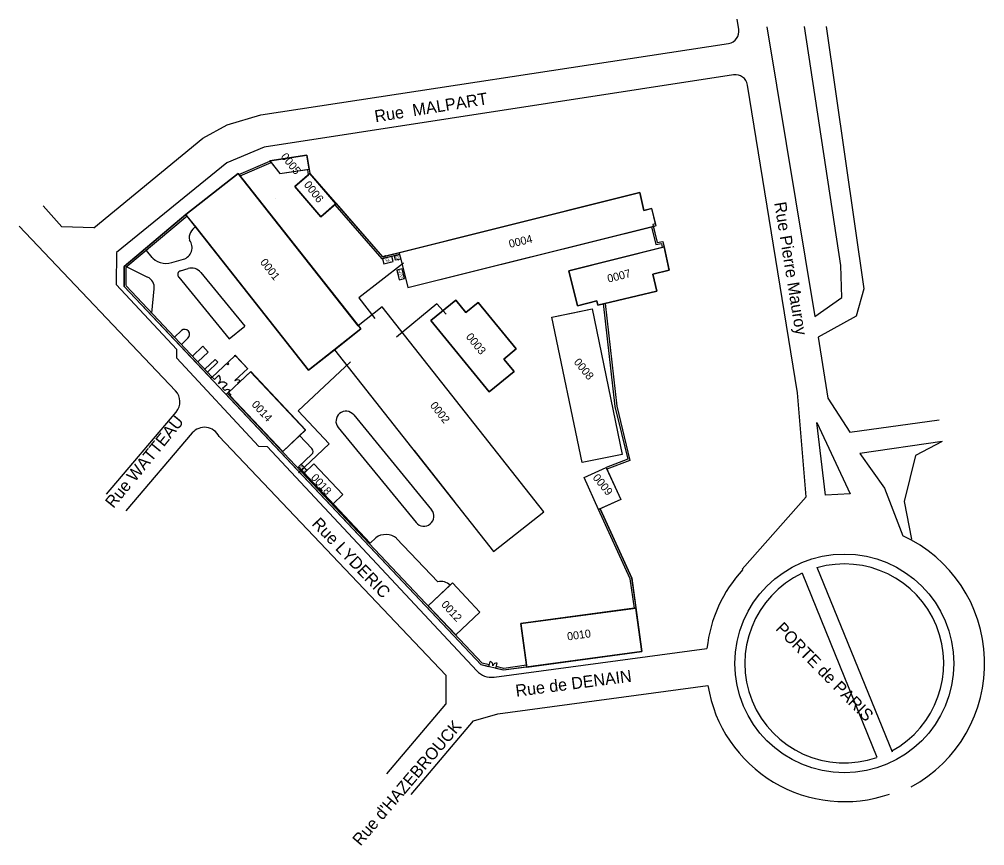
# Model space of a CAD drawing. Extents: x 703432 to 707394, y 7057985 to 7059523.
# Drawn here: x 703431.9 to 703673.1, y 7057985.3 to 7058191.7 of the extents above; entities that cross this region are included whole.
import ezdxf

# ---------------------------------------------------------------- set-up
doc = ezdxf.new("R2010")
doc.units = 0
for name, color, linetype in [('DH_HACHURE-MOTIF', 7, 'Continuous'), ('DH_TEXTE', 7, 'Continuous'), ('GEOSID_AIRE_AMENAGEE_POLYGONE', 7, 'Continuous'), ('GO_DALLE', 7, 'Continuous'), ('GO_MUR_EXTERIEUR', 7, 'Continuous'), ('IMM_LIMITE PHYSIQUE', 7, 'Continuous'), ('R_CH_PRIM_CANALISATION_CL_A', 7, 'Continuous'), ('R_IND_GAZ_NAT_CANALISATION_CL_A', 7, 'Continuous'), ('R_PLU_CANALISATION_CL_A', 7, 'Continuous'), ('RES_INCENDIE - EQUIP - TEXTE', 7, 'Continuous'), ('SID_NUMERO_BATI', 7, 'Continuous'), ('SID_POLYLIGNES_BATI', 7, 'Continuous'), ('SID_POLYLIGNES_IMMEUBLE', 7, 'Continuous'), ('VOIRIE_BORDURE', 7, 'Continuous'), ('VOIRIE_ROUTE', 7, 'Continuous')]:
    doc.layers.add(name, color=color, linetype=linetype)

msp = doc.modelspace()

# ---------------------------------------------------------------- linework, layer by layer
at = {"layer": 'DH_HACHURE-MOTIF'}
for p, q in [((703500.68, 7058149.94), (703504.1, 7058152.86)), ((703504.1, 7058152.86), (703504.48, 7058153.19)), ((703504.48, 7058153.19), (703510.98, 7058145.59)), ((703507.18, 7058142.34), (703500.68, 7058149.94)), ((703564.97, 7058117.3), (703569.88, 7058118.25)), ((703572.51, 7058080.96), (703564.97, 7058117.3)), ((703582.53, 7058082.98), (703572.51, 7058080.96)), ((703573, 7058077.21), (703578.53, 7058079.71)), ((703576.61, 7058069.22), (703573, 7058077.21)), ((703582.14, 7058071.72), (703576.61, 7058069.22))]:
    msp.add_line(p, q, dxfattribs=at)
for points in [[(703503.86, 7058154.19), (703504.3, 7058154.27), (703503.72, 7058157.72), (703494.45, 7058156.29), (703494.78, 7058155.89), (703497, 7058153.17), (703503.86, 7058154.19)], [(703473.77, 7058142.54), (703475.97, 7058139.76), (703504.16, 7058104.03), (703510.63, 7058109.14), (703517.19, 7058114.32), (703516.57, 7058115.1), (703486.83, 7058152.79), (703486.53, 7058153.18), (703473.5, 7058142.9), (703473.77, 7058142.54)], [(703526.88, 7058132.93), (703527.17, 7058131.79), (703528.95, 7058124.64), (703590.61, 7058140.04), (703591.04, 7058140.15), (703589.89, 7058144.43), (703587.95, 7058143.95), (703586.92, 7058148.4), (703550.06, 7058139.19), (703526.77, 7058133.37), (703526.88, 7058132.93)], [(703510.98, 7058145.59), (703510.64, 7058145.3), (703507.18, 7058142.34)], [(703576.15, 7058121.35), (703576.39, 7058120.28), (703591.14, 7058123.77), (703590.14, 7058127.99), (703594.28, 7058129.02), (703592.96, 7058134.81), (703592.52, 7058134.7), (703569.18, 7058128.87), (703571.36, 7058120.14), (703576.15, 7058121.35)], [(703524.99, 7058132.46), (703522.61, 7058131.86), (703522.93, 7058130.57), (703525.31, 7058131.17), (703524.99, 7058132.46)], [(703526.82, 7058126.62), (703528.11, 7058126.94), (703527.52, 7058129.32), (703526.23, 7058129), (703526.82, 7058126.62)], [(703543.45, 7058118.42), (703540.91, 7058121.51), (703534.72, 7058116.44), (703549.3, 7058098.65), (703555.49, 7058103.72), (703552.95, 7058106.82), (703556.05, 7058109.35), (703546.54, 7058120.95), (703543.45, 7058118.42)], [(703562.95, 7058068.66), (703522.57, 7058119.84), (703516.57, 7058115.1), (703517.19, 7058114.32), (703510.63, 7058109.14), (703550.39, 7058058.75), (703562.95, 7058068.66)], [(703569.88, 7058118.25), (703574.99, 7058119.31), (703582.53, 7058082.98)], [(703502.39, 7058080.46), (703502.33, 7058080.54), (703501.6, 7058079.85), (703503.02, 7058078.34), (703503.75, 7058079.03), (703502.39, 7058080.46)], [(703578.53, 7058079.71), (703578.62, 7058079.51), (703582.14, 7058071.72)], [(703539.51, 7058050.32), (703534.05, 7058045.16), (703540.91, 7058037.89), (703546.96, 7058043.59), (703540.1, 7058050.87), (703539.51, 7058050.32)], [(703558.6, 7058030.31), (703558.66, 7058029.86), (703587.4, 7058033.72), (703585.94, 7058044.62), (703585.49, 7058044.56), (703557.2, 7058040.77), (703558.6, 7058030.31)]]:
    msp.add_lwpolyline(points, dxfattribs=at)
for points in [[(703499.64, 7058085.57), (703503.36, 7058089.08), (703489.64, 7058103.63), (703484.12, 7058098.42), (703484.71, 7058097.8), (703484.54, 7058097.64), (703497.68, 7058083.71)], [(703505.47, 7058080.66), (703503.02, 7058078.34), (703510.26, 7058070.67), (703512.71, 7058072.98)]]:
    msp.add_lwpolyline(points, close=True, dxfattribs=at)
at = {"layer": 'GEOSID_AIRE_AMENAGEE_POLYGONE'}
msp.add_lwpolyline([(703525.9, 7058131.48), (703525.62, 7058132.62), (703526.88, 7058132.93), (703527.16, 7058131.79)], close=True, dxfattribs=at)
at = {"layer": 'GO_DALLE'}
msp.add_lwpolyline([(703526.88, 7058132.93), (703527.17, 7058131.79), (703525.9, 7058131.48), (703525.62, 7058132.62)], close=True, dxfattribs=at)
at = {"layer": 'GO_MUR_EXTERIEUR'}
for p, q in [((703503.72, 7058157.72), (703494.45, 7058156.29)), ((703504.3, 7058154.27), (703503.72, 7058157.72)), ((703494.45, 7058156.29), (703497, 7058153.17)), ((703473.5, 7058142.9), (703486.53, 7058153.18)), ((703486.53, 7058153.18), (703517.19, 7058114.32)), ((703497, 7058153.17), (703504.3, 7058154.27)), ((703504.48, 7058153.19), (703500.68, 7058149.94)), ((703510.98, 7058145.59), (703504.48, 7058153.19)), ((703500.68, 7058149.94), (703507.18, 7058142.34)), ((703500.68, 7058149.94), (703500.68, 7058149.94)), ((703586.92, 7058148.4), (703526.77, 7058133.37)), ((703587.95, 7058143.95), (703586.92, 7058148.4)), ((703507.18, 7058142.34), (703510.98, 7058145.59)), ((703504.16, 7058104.03), (703473.5, 7058142.9)), ((703589.89, 7058144.43), (703587.95, 7058143.95)), ((703591.04, 7058140.15), (703589.89, 7058144.43)), ((703528.95, 7058124.64), (703591.04, 7058140.15)), ((703526.77, 7058133.37), (703528.95, 7058124.64)), ((703569.18, 7058128.87), (703592.96, 7058134.81)), ((703592.96, 7058134.81), (703594.28, 7058129.02)), ((703571.36, 7058120.14), (703569.18, 7058128.87)), ((703594.28, 7058129.02), (703590.14, 7058127.99)), ((703590.14, 7058127.99), (703591.14, 7058123.77)), ((703534.72, 7058116.44), (703540.91, 7058121.51)), ((703540.91, 7058121.51), (703543.45, 7058118.42)), ((703543.45, 7058118.42), (703546.54, 7058120.95)), ((703546.54, 7058120.95), (703556.05, 7058109.35)), ((703522.57, 7058119.84), (703516.57, 7058115.1)), ((703562.95, 7058068.66), (703522.57, 7058119.84)), ((703564.97, 7058117.3), (703574.99, 7058119.31)), ((703574.99, 7058119.31), (703582.53, 7058082.98)), ((703549.3, 7058098.65), (703534.72, 7058116.44)), ((703572.51, 7058080.96), (703564.97, 7058117.3)), ((703517.19, 7058114.32), (703504.16, 7058104.03)), ((703517.19, 7058114.32), (703510.63, 7058109.14)), ((703516.57, 7058115.1), (703517.19, 7058114.32)), ((703510.63, 7058109.14), (703550.39, 7058058.75)), ((703556.05, 7058109.35), (703552.95, 7058106.82)), ((703552.95, 7058106.82), (703555.49, 7058103.72)), ((703489.68, 7058103.66), (703484.12, 7058098.42)), ((703503.4, 7058089.11), (703489.68, 7058103.66)), ((703555.49, 7058103.72), (703549.3, 7058098.65)), ((703497.68, 7058083.71), (703503.4, 7058089.11)), ((703582.53, 7058082.98), (703572.51, 7058080.96)), ((703501.6, 7058079.85), (703502.33, 7058080.54)), ((703502.33, 7058080.54), (703503.75, 7058079.03)), ((703503.02, 7058078.34), (703501.6, 7058079.85)), ((703503.75, 7058079.03), (703503.02, 7058078.34)), ((703573, 7058077.21), (703578.53, 7058079.71)), ((703578.53, 7058079.71), (703582.14, 7058071.72)), ((703576.61, 7058069.22), (703573, 7058077.21)), ((703582.14, 7058071.72), (703576.61, 7058069.22)), ((703550.39, 7058058.75), (703562.95, 7058068.66)), ((703534.05, 7058045.16), (703540.1, 7058050.87)), ((703540.1, 7058050.87), (703546.96, 7058043.59)), ((703540.91, 7058037.89), (703534.05, 7058045.16)), ((703557.2, 7058040.77), (703585.94, 7058044.62)), ((703585.94, 7058044.62), (703587.4, 7058033.72)), ((703546.96, 7058043.59), (703540.91, 7058037.89)), ((703558.66, 7058029.86), (703557.2, 7058040.77)), ((703587.4, 7058033.72), (703558.66, 7058029.86))]:
    msp.add_line(p, q, dxfattribs=at)
for points in [[(703522.61, 7058131.86), (703522.93, 7058130.57), (703525.31, 7058131.17), (703524.99, 7058132.46)], [(703527.52, 7058129.32), (703526.23, 7058129), (703526.82, 7058126.62), (703528.11, 7058126.94)], [(703505.47, 7058080.66), (703512.71, 7058072.98), (703510.26, 7058070.67), (703503.02, 7058078.34)]]:
    msp.add_lwpolyline(points, close=True, dxfattribs=at)
for points in [[(703591.14, 7058123.77), (703576.39, 7058120.28), (703576.15, 7058121.35), (703571.36, 7058120.14)], [(703484.12, 7058098.42), (703484.71, 7058097.8), (703484.54, 7058097.64), (703497.68, 7058083.71)]]:
    msp.add_lwpolyline(points, dxfattribs=at)
at = {"layer": 'IMM_LIMITE PHYSIQUE'}
for p, q in [((703486.74, 7058152.92), (703494.47, 7058156.25)), ((703487.04, 7058152.56), (703494.78, 7058155.89)), ((703503.86, 7058154.19), (703504.08, 7058152.85)), ((703504.3, 7058154.27), (703504.48, 7058153.19)), ((703510.7, 7058145.35), (703522.43, 7058131.81)), ((703511.04, 7058145.64), (703522.58, 7058132.32)), ((703473.5, 7058142.89), (703458.07, 7058129.92)), ((703473.79, 7058142.54), (703458.52, 7058129.71)), ((703526.77, 7058133.37), (703522.58, 7058132.32)), ((703526.89, 7058132.93), (703522.43, 7058131.81)), ((703458.07, 7058129.92), (703458.07, 7058124.97)), ((703458.52, 7058129.71), (703458.52, 7058125.17)), ((703593.8, 7058129.52), (703593.8, 7058129.52)), ((703458.07, 7058124.97), (703479.74, 7058102)), ((703458.54, 7058125.13), (703480.07, 7058102.31)), ((703480.07, 7058102.31), (703485.63, 7058107.56)), ((703485.72, 7058101.42), (703488.93, 7058104.45)), ((703480.07, 7058102.31), (703479.74, 7058102)), ((703480.07, 7058102.3), (703480.62, 7058101.72)), ((703480.62, 7058101.72), (703481.71, 7058102.75)), ((703482.68, 7058099.54), (703483.77, 7058100.57)), ((703482.68, 7058099.54), (703483.23, 7058098.95)), ((703485.72, 7058101.42), (703485.78, 7058101.36)), ((703487.05, 7058101.32), (703486.4, 7058100.7)), ((703486.4, 7058100.7), (703486.45, 7058100.64)), ((703483.91, 7058098.24), (703483.58, 7058097.93)), ((703483.58, 7058097.93), (703547.28, 7058030.41)), ((703484.5, 7058098.92), (703483.85, 7058098.3)), ((703483.85, 7058098.3), (703483.91, 7058098.24)), ((703483.91, 7058098.24), (703547.51, 7058030.81)), ((703549.21, 7058029.95), (703547.28, 7058030.41)), ((703549.31, 7058030.39), (703547.51, 7058030.81)), ((703549.21, 7058029.95), (703549.51, 7058031.24)), ((703550.96, 7058029.54), (703551.26, 7058030.83)), ((703552.89, 7058029.09), (703550.96, 7058029.54)), ((703552.91, 7058029.55), (703551.06, 7058029.98)), ((703558.66, 7058029.86), (703552.89, 7058029.09)), ((703558.6, 7058030.31), (703552.91, 7058029.55))]:
    msp.add_line(p, q, dxfattribs=at)
for points in [[(703589.85, 7058139.86), (703590.9, 7058135.39), (703592.3, 7058135.66), (703592.52, 7058134.71)], [(703590.29, 7058139.97), (703591.24, 7058135.91), (703592.64, 7058136.18), (703592.96, 7058134.81)], [(703577.78, 7058120.66), (703580.7, 7058094.94), (703583.92, 7058081.77), (703578.54, 7058079.71)], [(703578.22, 7058120.72), (703581.14, 7058095.02), (703584.45, 7058081.49), (703578.7, 7058079.29)], [(703585.55, 7058044.57), (703584.53, 7058051.91), (703576.62, 7058069.19)], [(703586, 7058044.63), (703584.96, 7058052.04), (703577.03, 7058069.38)]]:
    msp.add_lwpolyline(points, dxfattribs=at)
for points in [[(703485.79, 7058107.7), (703485.55, 7058107.65), (703485.72, 7058107.46)], [(703485.79, 7058107.7), (703488.95, 7058104.35), (703488.99, 7058104.39), (703485.83, 7058107.74)], [(703483.76, 7058105.64), (703483.96, 7058105.42), (703484.2, 7058105.65), (703484, 7058105.87)]]:
    msp.add_lwpolyline(points, close=True, dxfattribs=at)
for centre, radius, start, end in [((703480.62, 7058101.72), 1.5, 313.3307, 43.3307), ((703482.68, 7058099.54), 1.5, 43.3307, 133.3307), ((703486.4, 7058100.7), 0.9, 43.3307, 133.3307), ((703483.85, 7058098.3), 0.9, 43.3307, 133.3307), ((703549.34, 7058030.39), 0.874, 346.7916, 78.7098), ((703551.04, 7058029.99), 0.874, 75.2683, 166.7916)]:
    msp.add_arc(centre, radius, start, end, dxfattribs=at)
at = {"layer": 'R_CH_PRIM_CANALISATION_CL_A'}
for points in [[(703527.83, 7058130.75), (703516.68, 7058122.14), (703520.71, 7058116.92)], [(703538.54, 7058118.06), (703536.19, 7058120.58), (703526.14, 7058112.25)]]:
    msp.add_lwpolyline(points, dxfattribs=at)
at = {"layer": 'R_IND_GAZ_NAT_CANALISATION_CL_A'}
msp.add_lwpolyline([(703501.61, 7058078.39), (703509.33, 7058085.59), (703501.56, 7058093.91), (703514.66, 7058106.14)], dxfattribs=at)
at = {"layer": 'R_PLU_CANALISATION_CL_A'}
msp.add_line((703530.51, 7058083.95), (703540.63, 7058071.12), dxfattribs=at)
at = {"layer": 'RES_INCENDIE - EQUIP - TEXTE'}
msp.add_line((703495.87, 7058146.98), (703495.87, 7058146.98), dxfattribs=at)
at = {"layer": 'SID_POLYLIGNES_BATI'}
for p, q in [((703503.72, 7058157.72), (703494.45, 7058156.29)), ((703504.3, 7058154.27), (703503.72, 7058157.72)), ((703494.45, 7058156.29), (703497, 7058153.17)), ((703473.5, 7058142.9), (703486.53, 7058153.18)), ((703486.53, 7058153.18), (703517.19, 7058114.32)), ((703497, 7058153.17), (703504.3, 7058154.27)), ((703504.48, 7058153.19), (703500.68, 7058149.94)), ((703510.98, 7058145.59), (703504.48, 7058153.19)), ((703500.68, 7058149.94), (703507.18, 7058142.34)), ((703500.68, 7058149.94), (703500.68, 7058149.94)), ((703586.92, 7058148.4), (703526.77, 7058133.37)), ((703587.95, 7058143.95), (703586.92, 7058148.4)), ((703507.18, 7058142.34), (703510.98, 7058145.59)), ((703504.16, 7058104.03), (703473.5, 7058142.9)), ((703589.89, 7058144.43), (703587.95, 7058143.95)), ((703591.04, 7058140.15), (703589.89, 7058144.43)), ((703528.95, 7058124.64), (703591.04, 7058140.15)), ((703526.77, 7058133.37), (703528.95, 7058124.64)), ((703534.72, 7058116.44), (703540.91, 7058121.51)), ((703540.91, 7058121.51), (703543.45, 7058118.42)), ((703543.45, 7058118.42), (703546.54, 7058120.95)), ((703546.54, 7058120.95), (703556.05, 7058109.35)), ((703522.57, 7058119.84), (703516.57, 7058115.1)), ((703562.95, 7058068.66), (703522.57, 7058119.84)), ((703564.97, 7058117.3), (703574.99, 7058119.31)), ((703574.99, 7058119.31), (703582.53, 7058082.98)), ((703549.3, 7058098.65), (703534.72, 7058116.44)), ((703572.51, 7058080.96), (703564.97, 7058117.3)), ((703517.19, 7058114.32), (703504.16, 7058104.03)), ((703517.19, 7058114.32), (703510.63, 7058109.14)), ((703516.57, 7058115.1), (703517.19, 7058114.32)), ((703510.63, 7058109.14), (703550.39, 7058058.75)), ((703556.05, 7058109.35), (703552.95, 7058106.82)), ((703552.95, 7058106.82), (703555.49, 7058103.72)), ((703489.64, 7058103.63), (703484.12, 7058098.42)), ((703503.36, 7058089.08), (703489.64, 7058103.63)), ((703555.49, 7058103.72), (703549.3, 7058098.65)), ((703497.68, 7058083.71), (703503.36, 7058089.08)), ((703582.53, 7058082.98), (703572.51, 7058080.96)), ((703501.6, 7058079.85), (703502.33, 7058080.54)), ((703502.33, 7058080.54), (703503.75, 7058079.03)), ((703503.02, 7058078.34), (703501.6, 7058079.85)), ((703503.75, 7058079.03), (703503.02, 7058078.34)), ((703573, 7058077.21), (703578.53, 7058079.71)), ((703578.53, 7058079.71), (703582.14, 7058071.72)), ((703576.61, 7058069.22), (703573, 7058077.21)), ((703582.14, 7058071.72), (703576.61, 7058069.22)), ((703550.39, 7058058.75), (703562.95, 7058068.66)), ((703534.05, 7058045.16), (703540.1, 7058050.87)), ((703540.1, 7058050.87), (703546.96, 7058043.59)), ((703540.91, 7058037.89), (703534.05, 7058045.16)), ((703557.2, 7058040.77), (703585.94, 7058044.62)), ((703585.94, 7058044.62), (703587.4, 7058033.72)), ((703546.96, 7058043.59), (703540.91, 7058037.89)), ((703558.66, 7058029.86), (703557.2, 7058040.77)), ((703587.4, 7058033.72), (703558.66, 7058029.86))]:
    msp.add_line(p, q, dxfattribs=at)
for points in [[(703522.61, 7058131.86), (703522.93, 7058130.57), (703525.31, 7058131.17), (703524.99, 7058132.46)], [(703525.9, 7058131.48), (703525.62, 7058132.62), (703526.88, 7058132.93), (703527.17, 7058131.79)], [(703527.52, 7058129.32), (703526.23, 7058129), (703526.82, 7058126.62), (703528.11, 7058126.94)], [(703505.47, 7058080.66), (703512.71, 7058072.98), (703510.26, 7058070.67), (703503.02, 7058078.34)]]:
    msp.add_lwpolyline(points, close=True, dxfattribs=at)
msp.add_lwpolyline([(703484.12, 7058098.42), (703484.71, 7058097.8), (703484.54, 7058097.64), (703497.68, 7058083.71)], dxfattribs=at)
at = {"layer": 'SID_POLYLIGNES_IMMEUBLE'}
for p, q in [((703522.58, 7058132.32), (703586.92, 7058148.4)), ((703586.92, 7058148.4), (703587.95, 7058143.95)), ((703587.95, 7058143.95), (703589.85, 7058144.43)), ((703522.58, 7058132.32), (703522.58, 7058132.32)), ((703458.07, 7058124.97), (703458.07, 7058129.92)), ((703594.28, 7058129.02), (703590.14, 7058127.99)), ((703590.14, 7058127.99), (703591.14, 7058123.77)), ((703547.28, 7058030.41), (703458.07, 7058124.97)), ((703591.14, 7058123.77), (703578.22, 7058120.72)), ((703584.45, 7058081.49), (703578.7, 7058079.29)), ((703578.7, 7058079.29), (703582.14, 7058071.72)), ((703582.14, 7058071.72), (703577.03, 7058069.38)), ((703577.03, 7058069.38), (703584.96, 7058052.04)), ((703584.96, 7058052.04), (703587.4, 7058033.72))]:
    msp.add_line(p, q, dxfattribs=at)
for points in [[(703486.53, 7058153.18), (703486.74, 7058152.92), (703494.47, 7058156.25), (703494.45, 7058156.29), (703503.72, 7058157.72)], [(703503.72, 7058157.72), (703504.48, 7058153.19), (703522.58, 7058132.32)], [(703458.07, 7058129.92), (703473.5, 7058142.9), (703486.53, 7058153.18)], [(703589.85, 7058144.43), (703590.75, 7058140.59), (703590.18, 7058140.44), (703591.24, 7058135.91), (703592.64, 7058136.18), (703594.28, 7058129.02)], [(703578.22, 7058120.72), (703581.14, 7058095.02), (703584.45, 7058081.49)], [(703587.4, 7058033.72), (703552.89, 7058029.09), (703547.28, 7058030.41)]]:
    msp.add_lwpolyline(points, dxfattribs=at)
at = {"layer": 'VOIRIE_BORDURE'}
for p, q in [((703463.53, 7058133.92), (703464.95, 7058132.2)), ((703469.21, 7058130.67), (703469.21, 7058130.67)), ((703469.96, 7058130.89), (703472.87, 7058131.74)), ((703458.71, 7058129.87), (703463.93, 7058127.3)), ((703472.18, 7058128.88), (703474.05, 7058129.41)), ((703477.21, 7058128.44), (703488.18, 7058115.06)), ((703471.69, 7058127.29), (703484.31, 7058111.89)), ((703464.99, 7058118.29), (703465.59, 7058124.31)), ((703470.65, 7058112.29), (703472.39, 7058113.93)), ((703484.31, 7058111.89), (703488.18, 7058115.06)), ((703472.37, 7058110.47), (703474.02, 7058112.03)), ((703475.11, 7058107.56), (703477.7, 7058110)), ((703479.07, 7058108.54), (703477.7, 7058110)), ((703476.49, 7058106.1), (703479.07, 7058108.54)), ((703478.2, 7058104.29), (703480.78, 7058106.72)), ((703481.47, 7058105.99), (703480.78, 7058106.72)), ((703478.89, 7058103.56), (703481.47, 7058105.99)), ((703515.43, 7058092.87), (703534.88, 7058069.13)), ((703511.56, 7058089.7), (703531.01, 7058065.96)), ((703501.91, 7058087.7), (703505, 7058084.43)), ((703504.95, 7058083.02), (703501.6, 7058079.85)), ((703501.6, 7058079.85), (703519.53, 7058060.84)), ((703519.53, 7058060.84), (703520.93, 7058062.16)), ((703526.15, 7058062.01), (703536.42, 7058051.12))]:
    msp.add_line(p, q, dxfattribs=at)
for centre, radius, start, end in [((703477.33, 7058137.11), 3, 115.4761, 192.4737), ((703472.03, 7058134.62), 3, 286.3025, 37.942), ((703468.55, 7058135.69), 5, 219.5679, 286.3025), ((703472.45, 7058127.91), 1, 106.0656, 219.3307), ((703474.88, 7058126.53), 3, 39.3307, 106.0656), ((703462.61, 7058124.61), 3, 354.3306, 63.7442), ((703473.18, 7058112.96), 1.25, 312.1096, 129.3307), ((703513.49, 7058091.28), 2.5, 39.3307, 219.3307), ((703504.27, 7058083.74), 1, 313.3306, 43.3306), ((703532.95, 7058067.55), 2.5, 219.3307, 39.3307), ((703537.33, 7058048.26), 3, 43.3308, 107.6513)]:
    msp.add_arc(centre, radius, start, end, dxfattribs=at)
msp.add_ellipse((703523.45, 7058059.98), major_axis=(-3.68, 0), ratio=0.816097, start_param=3.897855, end_param=5.468654, dxfattribs=at)
at = {"layer": 'VOIRIE_ROUTE'}
for p, q in [((703470.91, 7058098.9), (703431.87, 7058139.97)), ((703450.51, 7058139.62), (703442.49, 7058139.83)), ((703456.13, 7058133.41), (703456.08, 7058125.46)), ((703456.08, 7058125.46), (703471.26, 7058109.2)), ((703471.19, 7058106.99), (703471.26, 7058109.2)), ((703471.19, 7058106.99), (703491.66, 7058085.06)), ((703453.68, 7058073.08), (703471.06, 7058093.55)), ((703458.6, 7058068.9), (703475.11, 7058088.35)), ((703538.48, 7058027.81), (703481.77, 7058087.47)), ((703491.66, 7058085.06), (703493.9, 7058084.99)), ((703493.84, 7058085), (703546.17, 7058028.92)), ((703639.47, 7058073.18), (703633.28, 7058072.81)), ((703628.46, 7058072.39), (703612.5, 7058054.36)), ((703631.11, 7058054.83), (703649.94, 7058008.73)), ((703627.49, 7058053.35), (703646.14, 7058007.36)), ((703538.48, 7058027.81), (703538.45, 7058020.59)), ((703523.72, 7058003.21), (703538.45, 7058020.59))]:
    msp.add_line(p, q, dxfattribs=at)
for points in [[(703611.66, 7058189.13), (703611.28, 7058191.67)], [(703618.68, 7058189.76), (703630.67, 7058117.41), (703637.37, 7058122.18), (703637.11, 7058130.18), (703628.09, 7058189.89)], [(703633.5, 7058189.89), (703642.91, 7058124.37), (703640.98, 7058117.54), (703631.44, 7058112.25), (703633.89, 7058097.03), (703639.43, 7058088.52), (703661.74, 7058091.66)], [(703450.51, 7058139.62), (703477.73, 7058161.99), (703483.77, 7058165.28), (703492.22, 7058167.82), (703609.11, 7058185.66)], [(703610.36, 7058177.78), (703493.07, 7058159.75), (703483.72, 7058155.79), (703456.13, 7058133.41)], [(703628.46, 7058072.39), (703626.31, 7058098.4), (703613.83, 7058175.26)], [(703442.49, 7058139.83), (703437.81, 7058145.06)], [(703633.28, 7058072.81), (703631.13, 7058090.92), (703639.47, 7058073.18)], [(703662.5, 7058086.2), (703641.88, 7058083.24), (703648.02, 7058074.56), (703652.62, 7058062.67)], [(703662.5, 7058086.2), (703655.8, 7058082.72), (703652.97, 7058071.24), (703654.82, 7058061.83)], [(703550.49, 7058027.38), (703603.68, 7058034.53)], [(703529.79, 7057998.06), (703545.34, 7058016.4), (703551.4, 7058018.21), (703603.92, 7058025.27)]]:
    msp.add_lwpolyline(points, dxfattribs=at)
msp.add_circle((703638.02, 7058030.78), 27.33, dxfattribs=at)
for centre, radius, start, end in [((703608.65, 7058188.67), 3.05, 278.6767, 8.6767), ((703610.82, 7058174.77), 3.05, 9.2218, 98.7403), ((703468.01, 7058096.14), 4, 319.6675, 43.547), ((703478.15, 7058085.76), 4, 25.2763, 139.6675), ((703638.02, 7058030.78), 35.08, 298.459, 65.3951), ((703638.02, 7058030.78), 34.53, 137.2612, 173.7773), ((703638.02, 7058030.78), 24.85, 298.459, 105.9703), ((703638.02, 7058030.78), 24.85, 115.0132, 289.1455), ((703549.82, 7058032.34), 5, 223.0213, 277.6524), ((703638.02, 7058030.78), 34.53, 189.1939, 289.1455)]:
    msp.add_arc(centre, radius, start, end, dxfattribs=at)

# ---------------------------------------------------------------- texts
at = {"layer": 'DH_TEXTE'}
for s, rotation, p in [('Rue  MALPART', 9.1668, (703520.89, 7058165.92)), ('Rue Pierre Mauroy', 279.2071, (703620.49, 7058145.83)), ('Rue WATTEAU', 50.7423, (703455.38, 7058069.36)), ('Rue LYDERIC', 313.8024, (703504.78, 7058065.48)), ('PORTE de PARIS', 314.4253, (703620.64, 7058039.29)), ('Rue de DENAIN', 7.4746, (703556.06, 7058022.44)), ("Rue d'HAZEBROUCK", 49.6268, (703517.11, 7057985))]:
    msp.add_text(s, height=3, rotation=rotation, dxfattribs=at).set_placement(p)
at = {"layer": 'SID_NUMERO_BATI'}
for s, height, rotation, p in [('0005', 2, 309.3307, (703497.08, 7058157.3)), ('0006', 2, 307.9879, (703502.85, 7058150.33)), ('0004', 2, 13.5243, (703554.46, 7058134.56)), ('0021', 0.702, 308.0308, (703525.31, 7058132.92)), ('0001', 2, 308.2727, (703491.91, 7058130.94)), ('0020', 0.738, 308.0308, (703522.7, 7058132.45)), ('0019', 0.866, 308.0308, (703526, 7058128.7)), ('0007', 2, 14.5051, (703579.08, 7058125.86)), ('0003', 2, 309.3307, (703543.34, 7058112.31)), ('0008', 2, 309.3307, (703570.29, 7058105.99)), ('0014', 2, 312.5129, (703489.78, 7058095.35)), ('0002', 2, 308.2727, (703534.37, 7058095.18)), ('0013', 0.698, 312.5129, (703501.64, 7058080.03)), ('0018', 2, 312.5129, (703504.59, 7058077.05)), ('0009', 2, 309.3307, (703575.01, 7058077.12)), ('0012', 2, 312.5129, (703537.16, 7058045.38)), ('0010', 2, 8.0003, (703568.9, 7058036.51))]:
    msp.add_text(s, height=height, rotation=rotation, dxfattribs=at).set_placement(p)

doc.saveas('drawing.dxf')
